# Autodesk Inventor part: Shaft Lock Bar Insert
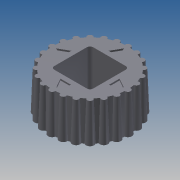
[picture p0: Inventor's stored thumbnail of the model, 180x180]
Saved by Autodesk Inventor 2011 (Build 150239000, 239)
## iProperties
Created: 2010-06
Part Number: Shaft Lock Bar Insert
Document SubType Name: Modeling
Designer: Phil
Density: 1 g/cm^3
Author: Phil
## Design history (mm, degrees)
sketch "Sketch1"
  geometry: L1 (-5.486, 0.876)-(-3.962, 0) reference; L2 (-3.962, 0)-(-5.486, -0.876) reference; L3 (-5.486, -0.876)-(-5.486, 0.876) reference; L4 (3.791, -5.025)-(16.487, -5.025) reference; L5 (16.487, -5.025)-(17.725, -3.787) reference; L6 (17.725, -3.787)-(17.725, 3.787) reference; L7 (17.725, 3.787)-(16.487, 5.025) reference; L8 (16.487, 5.025)-(3.791, 5.025) reference; L9 (-3.791, 5.025)-(-16.487, 5.025) reference; L10 (-16.487, 5.025)-(-17.725, 3.787) reference; L11 (-17.725, 3.787)-(-17.725, -3.787) reference; L12 (-17.725, -3.787)-(-16.487, -5.025) reference; L13 (-16.487, -5.025)-(-3.791, -5.025) reference; C1 r 1 at (5.889, 0) reference; C2 r 2.311 at (-12.7, 0) reference; C3 r 2.311 at (12.7, 0) reference; A1 r 3.106 centre (0, 0) between (-3.099, -0.22) and (-3.05, -0.59) reference; A2 r 0.224 centre (-3.14, 0) between (-3.099, 0.22) and (-3.099, -0.22) reference; A3 r 3.106 centre (0, 0) between (-3.05, 0.59) and (-3.099, 0.22) reference; A4 r 0.224 centre (-3.033, 0.813) between (-2.936, 1.014) and (-3.05, 0.59) reference; A5 r 3.106 centre (0, 0) between (-2.793, 1.359) and (-2.936, 1.014) reference; A6 r 0.224 centre (-2.719, 1.57) between (-2.574, 1.74) and (-2.793, 1.359) reference; A7 r 3.106 centre (0, 0) between (-2.346, 2.036) and (-2.574, 1.74) reference; A8 r 0.224 centre (-2.22, 2.22) between (-2.036, 2.346) and (-2.346, 2.036) reference; A9 r 3.106 centre (0, 0) between (-1.74, 2.574) and (-2.036, 2.346) reference; A10 r 0.224 centre (-1.57, 2.719) between (-1.359, 2.793) and (-1.74, 2.574) reference; A11 r 3.106 centre (0, 0) between (-1.014, 2.936) and (-1.359, 2.793) reference; A12 r 0.224 centre (-0.813, 3.033) between (-0.59, 3.05) and (-1.014, 2.936) reference; A13 r 3.106 centre (0, 0) between (-0.22, 3.099) and (-0.59, 3.05) reference; A14 r 0.224 centre (0, 3.14) between (0.22, 3.099) and (-0.22, 3.099) reference; A15 r 3.106 centre (0, 0) between (0.589, 3.05) and (0.22, 3.099) reference; A16 r 0.224 centre (0.812, 3.03) between (1.015, 2.936) and (0.589, 3.05) reference; A17 r 3.106 centre (0, 0) between (1.359, 2.794) and (1.015, 2.936) reference; A18 r 0.224 centre (1.568, 2.717) between (1.74, 2.573) and (1.359, 2.794) reference; A19 r 3.106 centre (0, 0) between (2.035, 2.347) and (1.74, 2.573) reference; A20 r 0.224 centre (2.218, 2.218) between (2.347, 2.035) and (2.035, 2.347) reference; A21 r 3.106 centre (0, 0) between (2.573, 1.74) and (2.347, 2.035) reference; A22 r 0.224 centre (2.717, 1.568) between (2.794, 1.359) and (2.573, 1.74) reference; A23 r 3.106 centre (0, 0) between (2.936, 1.015) and (2.794, 1.359) reference; A24 r 0.224 centre (3.03, 0.812) between (3.05, 0.589) and (2.936, 1.015) reference; A25 r 3.106 centre (0, 0) between (3.099, 0.22) and (3.05, 0.589) reference; A26 r 0.224 centre (3.137, 0) between (3.099, -0.22) and (3.099, 0.22) reference; A27 r 3.106 centre (0, 0) between (3.05, -0.59) and (3.099, -0.22) reference; A28 r 0.224 centre (3.033, -0.813) between (2.936, -1.014) and (3.05, -0.59) reference; A29 r 3.106 centre (0, 0) between (2.793, -1.359) and (2.936, -1.014) reference; A30 r 0.224 centre (2.719, -1.57) between (2.574, -1.74) and (2.793, -1.359) reference; A31 r 3.106 centre (0, 0) between (2.346, -2.036) and (2.574, -1.74) reference; A32 r 0.224 centre (2.22, -2.22) between (2.036, -2.346) and (2.346, -2.036) reference; A33 r 3.106 centre (0, 0) between (1.74, -2.574) and (2.036, -2.346) reference; A34 r 0.224 centre (1.57, -2.719) between (1.359, -2.793) and (1.74, -2.574) reference; A35 r 3.106 centre (0, 0) between (1.014, -2.936) and (1.359, -2.793) reference; A36 r 0.224 centre (0.813, -3.033) between (0.59, -3.05) and (1.014, -2.936) reference; A37 r 3.106 centre (0, 0) between (0.22, -3.099) and (0.59, -3.05) reference; A38 r 0.224 centre (0, -3.14) between (-0.22, -3.099) and (0.22, -3.099) reference; A39 r 3.106 centre (0, 0) between (-0.59, -3.05) and (-0.22, -3.099) reference; A40 r 0.224 centre (-0.813, -3.033) between (-1.014, -2.936) and (-0.59, -3.05) reference; A41 r 3.106 centre (0, 0) between (-1.359, -2.793) and (-1.014, -2.936) reference; A42 r 0.224 centre (-1.57, -2.719) between (-1.74, -2.574) and (-1.359, -2.793) reference; A43 r 3.106 centre (0, 0) between (-2.036, -2.346) and (-1.74, -2.574) reference; A44 r 0.224 centre (-2.22, -2.22) between (-2.346, -2.036) and (-2.036, -2.346) reference; A45 r 3.106 centre (0, 0) between (-2.574, -1.74) and (-2.346, -2.036) reference; A46 r 0.224 centre (-2.719, -1.57) between (-2.793, -1.359) and (-2.574, -1.74) reference; A47 r 3.106 centre (0, 0) between (-2.936, -1.014) and (-2.793, -1.359) reference; A48 r 0.224 centre (-3.033, -0.813) between (-3.05, -0.59) and (-2.936, -1.014) reference; A49 r 6.295 centre (0, 0) between (3.791, 5.025) and (-3.791, 5.025) reference; A50 r 6.295 centre (0, 0) between (-3.791, -5.025) and (3.791, -5.025) reference; 1 further point
extrude "Extrusion1" new body sketch "Sketch1" distance "d0" = 3.175; taper "d1" = 2 deg
sketch "Sketch3"
  geometry: L1 (1.362, -1.612)-(-1.363, -1.612); L2 (-1.613, -1.362)-(-1.613, 1.363); L3 (-1.363, 1.613)-(1.362, 1.613); L4 (1.612, 1.363)-(1.612, -1.362); A1 r 0.25 centre (-1.363, -1.362) between (-1.613, -1.362) and (-1.363, -1.612); A2 r 0.25 centre (-1.363, 1.363) between (-1.363, 1.613) and (-1.613, 1.363); A3 r 0.25 centre (1.362, 1.363) between (1.612, 1.363) and (1.362, 1.613); A4 r 0.25 centre (1.362, -1.362) between (1.362, -1.612) and (1.612, -1.362); 1 further point
  constraints: 8 end point, 8 point on circle, 4 centre point
extrude "Extrusion3" cut sketch "Sketch3" stored distance "d4" = 0.127; taper "d5" = 0 deg
sketch "Sketch4"
  geometry: L1 (0, -2.8)-(-0.45, -2); L2 (-0.45, -2)-(0.45, -2); L3 (0, -2.8)-(-0.45, -2); L4 (-0.45, -2)-(0.45, -2); L5 (0.45, -2)-(0, -2.8); L6 (0.45, -2)-(0, -2.8); L7 (2.8, 0)-(2, -0.45); L8 (2, -0.45)-(2, 0.45); L9 (2.8, 0)-(2, 0.45); L10 (2, 0.45)-(2.8, 0); L11 (2.8, 0)-(2, -0.45); L12 (2, -0.45)-(2, 0.45); L13 (2.8, 0)-(2, 0.45); L14 (2, 0.45)-(2.8, 0); L15 (0.45, 2)-(-0.45, 2); L16 (-0.45, 2)-(0, 2.8); L17 (0, 2.8)-(0.45, 2); L18 (-2, 0.45)-(-2, -0.45); L19 (-2, -0.45)-(-2.8, 0); L20 (-2.8, 0)-(-2, 0.45); 44 further points
  constraints: 40 end point
extrude "Extrusion4" cut sketch "Sketch4" distance "d6" = 0.127; taper "d7" = 0 deg
body "Solid1"
node "Reference1"
